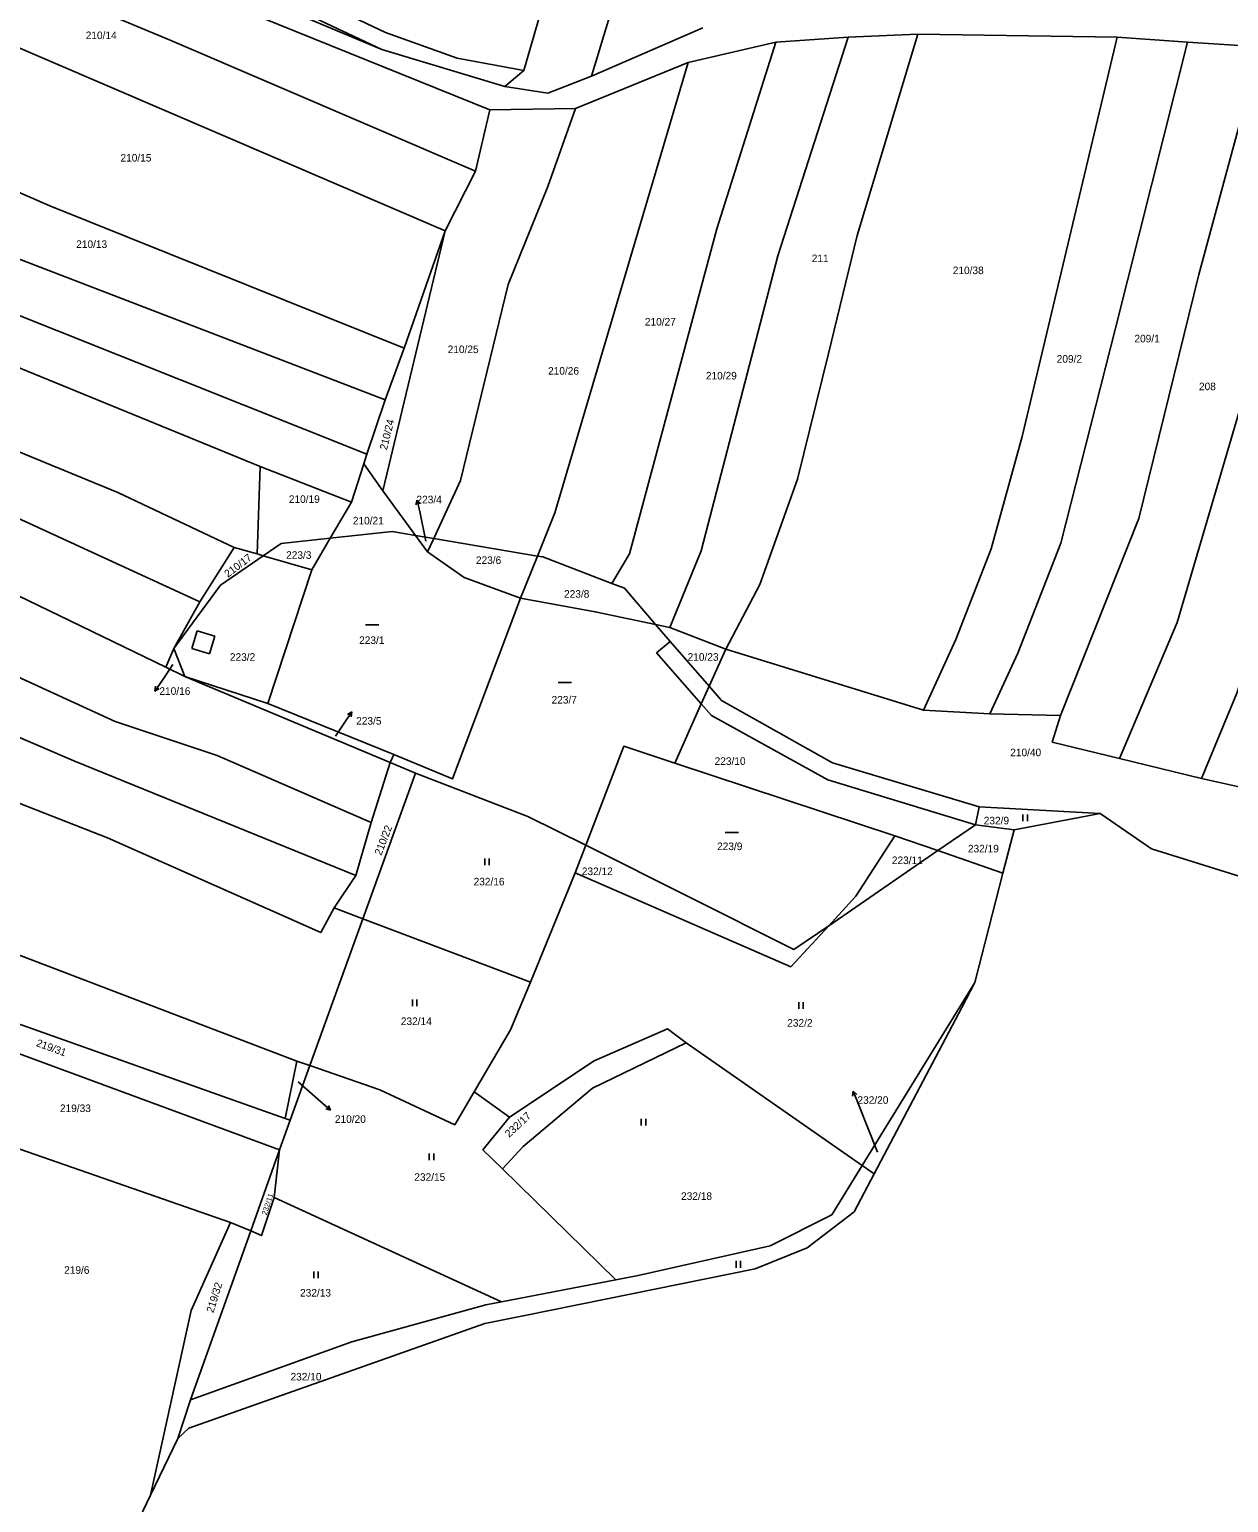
# Model space of a CAD drawing. Extents: x -746176 to -739709, y -1128407 to -1124482.
# Drawn here: x -742743.6 to -742474.2, y -1128024.5 to -1127693.8 of the extents above; entities that cross this region are included whole.
import ezdxf

# ---------------------------------------------------------------- set-up
doc = ezdxf.new("R2010")
doc.units = 0
for name, color, linetype in [('Vrstva 33', 7, 'Continuous'), ('Vrstva 42', 7, 'Continuous'), ('Vrstva 43', 7, 'Continuous'), ('Vrstva 44', 7, 'Continuous'), ('Vrstva 47', 7, 'Continuous')]:
    doc.layers.add(name, color=color, linetype=linetype)

msp = doc.modelspace()

# ---------------------------------------------------------------- linework, layer by layer
at = {"layer": 'Vrstva 33'}
for p, q in [((-742632.48, -1127703.04), (-742626.86, -1127683.46)), ((-742617.34, -1127704.25), (-742592.33, -1127693.42)), ((-742575.9, -1127696.61), (-742595.59, -1127701.21)), ((-742559.67, -1127695.56), (-742575.9, -1127696.61)), ((-742559.67, -1127695.56), (-742544.01, -1127694.88)), ((-742499.23, -1127695.56), (-742544.01, -1127694.88)), ((-742483.38, -1127696.63), (-742499.23, -1127695.56)), ((-742467.04, -1127697.67), (-742483.38, -1127696.63)), ((-742636.82, -1127706.57), (-742664.42, -1127698.33)), ((-742632.48, -1127703.04), (-742636.82, -1127706.57)), ((-742595.59, -1127701.21), (-742620.93, -1127711.51)), ((-742643.36, -1127725.63), (-742640.13, -1127711.82)), ((-742620.93, -1127711.51), (-742640.13, -1127711.82)), ((-742650.2, -1127739.03), (-742643.36, -1127725.63)), ((-742663.65, -1127776.96), (-742792.35, -1127727.57)), ((-742664.19, -1127797.36), (-742650.2, -1127739.03)), ((-742659.43, -1127765.34), (-742650.2, -1127739.03)), ((-742663.65, -1127776.96), (-742659.43, -1127765.34)), ((-742667.79, -1127789.16), (-742663.65, -1127776.96)), ((-742668.48, -1127791.31), (-742667.79, -1127789.16)), ((-742692.45, -1127811.55), (-742691.75, -1127791.9)), ((-742691.75, -1127791.9), (-742671.24, -1127799.9)), ((-742671.24, -1127799.9), (-742668.48, -1127791.31)), ((-742664.19, -1127797.36), (-742668.48, -1127791.31)), ((-742656.82, -1127807.4), (-742664.19, -1127797.36)), ((-742675.99, -1127807.99), (-742671.24, -1127799.9)), ((-742675.99, -1127807.99), (-742680.15, -1127815.09)), ((-742656.82, -1127807.4), (-742652.76, -1127808.09)), ((-742654.13, -1127811.06), (-742656.82, -1127807.4)), ((-742654.13, -1127811.06), (-742652.76, -1127808.09)), ((-742652.76, -1127808.09), (-742629.43, -1127812.04)), ((-742705.33, -1127822.31), (-742697.57, -1127810.08)), ((-742697.57, -1127810.08), (-742692.45, -1127811.55)), ((-742691.07, -1127811.95), (-742692.45, -1127811.55)), ((-742680.15, -1127815.09), (-742691.07, -1127811.95)), ((-742633.23, -1127821.48), (-742629.43, -1127812.04)), ((-742680.15, -1127815.09), (-742690.04, -1127845.16)), ((-742711.14, -1127832.79), (-742705.33, -1127822.31)), ((-742599.71, -1127828.08), (-742602.93, -1127827.4)), ((-742587.17, -1127832.97), (-742599.71, -1127828.08)), ((-742712.92, -1127837.01), (-742711.14, -1127832.79)), ((-742708.67, -1127839.06), (-742711.14, -1127832.79)), ((-742590.87, -1127841.26), (-742587.17, -1127832.97)), ((-742587.17, -1127832.97), (-742542.71, -1127846.65)), ((-742708.67, -1127839.06), (-742712.92, -1127837.01)), ((-742662.54, -1127858.41), (-742708.67, -1127839.06)), ((-742708.67, -1127839.06), (-742690.04, -1127845.16)), ((-742690.04, -1127845.16), (-742661.69, -1127856.62)), ((-742542.71, -1127846.65), (-742527.8, -1127847.44)), ((-742527.8, -1127847.44), (-742511.96, -1127847.84)), ((-742666.84, -1127871.89), (-742662.54, -1127858.41)), ((-742662.54, -1127858.41), (-742661.69, -1127856.62)), ((-742656.86, -1127860.79), (-742662.54, -1127858.41)), ((-742549.19, -1127874.82), (-742598.57, -1127858.52)), ((-742498.72, -1127857.52), (-742480.24, -1127862.01)), ((-742668.67, -1127893.45), (-742656.86, -1127860.79)), ((-742480.24, -1127862.01), (-742451.26, -1127868.39)), ((-742531.05, -1127872.36), (-742530.23, -1127868.37)), ((-742530.23, -1127868.37), (-742503.01, -1127869.85)), ((-742670.28, -1127883.77), (-742666.84, -1127871.89)), ((-742539.51, -1127878.17), (-742531.05, -1127872.36)), ((-742522.38, -1127873.53), (-742531.05, -1127872.36)), ((-742503.01, -1127869.85), (-742522.38, -1127873.53)), ((-742491.5, -1127877.75), (-742503.01, -1127869.85)), ((-742549.19, -1127874.82), (-742539.51, -1127878.17)), ((-742522.38, -1127873.53), (-742524.88, -1127883.24)), ((-742618.61, -1127876.98), (-742620.99, -1127883.17)), ((-742539.51, -1127878.17), (-742564.03, -1127895.02)), ((-742524.88, -1127883.24), (-742539.51, -1127878.17)), ((-742426.38, -1127898.15), (-742491.5, -1127877.75)), ((-742675.1, -1127891.02), (-742670.28, -1127883.77)), ((-742620.99, -1127883.17), (-742630.99, -1127907.7)), ((-742524.88, -1127883.24), (-742531.2, -1127907.76)), ((-742668.67, -1127893.45), (-742675.1, -1127891.02)), ((-742680.6, -1127926.45), (-742668.67, -1127893.45)), ((-742630.99, -1127907.7), (-742668.67, -1127893.45)), ((-742802.25, -1127897.14), (-742686.17, -1127938.31)), ((-742795.76, -1127905.39), (-742687.4, -1127945.34)), ((-742556.49, -1127948.86), (-742531.2, -1127907.76)), ((-742531.2, -1127907.76), (-742534.15, -1127913.36)), ((-742534.15, -1127913.36), (-742553.06, -1127949.33)), ((-742596.01, -1127921.34), (-742556.49, -1127948.86)), ((-742686.17, -1127938.31), (-742683.5, -1127925.44)), ((-742685.04, -1127938.71), (-742680.6, -1127926.45)), ((-742683.5, -1127925.44), (-742680.6, -1127926.45)), ((-742698.39, -1127961.68), (-742775.86, -1127934.72)), ((-742643.67, -1127932.31), (-742635.75, -1127937.99)), ((-742686.17, -1127938.31), (-742685.04, -1127938.71)), ((-742687.4, -1127945.34), (-742685.04, -1127938.71)), ((-742693.88, -1127963.5), (-742687.4, -1127945.34)), ((-742688.57, -1127956.03), (-742687.4, -1127945.34)), ((-742611.87, -1127974.55), (-742637.32, -1127949.65)), ((-742553.8, -1127950.73), (-742556.49, -1127948.86)), ((-742553.06, -1127949.33), (-742553.8, -1127950.73)), ((-742637.54, -1127979.49), (-742688.57, -1127956.03)), ((-742693.88, -1127963.5), (-742698.39, -1127961.68)), ((-742707.43, -1128001.51), (-742693.88, -1127963.5)), ((-742611.87, -1127974.55), (-742637.54, -1127979.49)), ((-742580.51, -1127972.05), (-742608.61, -1127977.73)), ((-742641.25, -1127984.32), (-742707.81, -1128007.87)), ((-742707.43, -1128001.51), (-742710.24, -1128010.19)), ((-742707.81, -1128007.87), (-742710.24, -1128010.19)), ((-742710.24, -1128010.19), (-742716.39, -1128022.92)), ((-742716.39, -1128022.92), (-742728.18, -1128047.33))]:
    msp.add_line(p, q, dxfattribs=at)
for points in [[(-742617.34, -1127704.25), (-742592.59, -1127622.78), (-742562.59, -1127531.26), (-742547.11, -1127485.27), (-742537.81, -1127453.81)], [(-742849.54, -1127613.47), (-742848.76, -1127613.6), (-742786.4, -1127635.17), (-742756.11, -1127640.29), (-742704.21, -1127675.14), (-742663.56, -1127694.46), (-742647.49, -1127700.26), (-742632.48, -1127703.04)], [(-742664.42, -1127698.33), (-742705.7, -1127678.8), (-742757.77, -1127644.27), (-742759.53, -1127644.48)], [(-742763.36, -1127654.17), (-742748.4, -1127660.64), (-742692.32, -1127686.56), (-742664.42, -1127698.33)], [(-742640.13, -1127711.82), (-742707.48, -1127684.6), (-742751.48, -1127663.32), (-742764.73, -1127657.63)], [(-742643.36, -1127725.63), (-742711.98, -1127696.17), (-742770.35, -1127671.87)], [(-742775.45, -1127684.77), (-742763.82, -1127690.28), (-742650.2, -1127739.03)], [(-742612.72, -1127818.18), (-742608.79, -1127811.54), (-742589.16, -1127738.55), (-742575.9, -1127696.61)], [(-742599.71, -1127828.08), (-742592.67, -1127810.85), (-742575.45, -1127744.63), (-742559.67, -1127695.56)], [(-742544.01, -1127694.88), (-742557.6, -1127740.07), (-742564.08, -1127766.54), (-742571.03, -1127794.76), (-742579.48, -1127818.4), (-742587.17, -1127832.97)], [(-742499.23, -1127695.56), (-742520.53, -1127785.2), (-742527.52, -1127810.4), (-742535.44, -1127830.74), (-742542.71, -1127846.65)], [(-742483.38, -1127696.63), (-742499.62, -1127760.84), (-742511.87, -1127809.1), (-742521.5, -1127833.81), (-742527.8, -1127847.44)], [(-742467.04, -1127697.67), (-742480.9, -1127748.82), (-742494.32, -1127803.6), (-742511.96, -1127847.84)], [(-742449.94, -1127699.44), (-742466.13, -1127760.26), (-742485.77, -1127826.93), (-742498.72, -1127857.52)], [(-742629.43, -1127812.04), (-742625.54, -1127802.36), (-742595.59, -1127701.21)], [(-742432.12, -1127702.08), (-742464.27, -1127819.17), (-742472.32, -1127842.8), (-742480.24, -1127862.01)], [(-742878.82, -1127704.23), (-742859.56, -1127712.24), (-742858.85, -1127709.24), (-742793.05, -1127739.22), (-742667.79, -1127789.16)], [(-742636.82, -1127706.57), (-742627.13, -1127708.08), (-742617.34, -1127704.25)], [(-742691.75, -1127791.9), (-742786.9, -1127753.03), (-742859.54, -1127721.45), (-742886.72, -1127710.02)], [(-742659.43, -1127765.34), (-742739.02, -1127733.43), (-742786.49, -1127712.73)], [(-742652.76, -1127808.09), (-742646.74, -1127795.08), (-742636.01, -1127751.08), (-742627.15, -1127729.06), (-742620.93, -1127711.51)], [(-742697.57, -1127810.08), (-742723.74, -1127797.75), (-742779.52, -1127774.85), (-742849.36, -1127744.61), (-742849.6, -1127747), (-742896.29, -1127726.42), (-742905.07, -1127723.45)], [(-742705.33, -1127822.31), (-742752.11, -1127800.85), (-742855.88, -1127756.96), (-742856.57, -1127758.28), (-742916.95, -1127732.14)], [(-742929.76, -1127741.52), (-742892.25, -1127757.26), (-742839.56, -1127779.37), (-742839.56, -1127777.92), (-742777.16, -1127805.95), (-742712.92, -1127837.01)], [(-742942.9, -1127751.14), (-742921.78, -1127760.46), (-742847.12, -1127793.15), (-742812.02, -1127809), (-742724.3, -1127849.19), (-742701.43, -1127856.81), (-742666.84, -1127871.89)], [(-742670.28, -1127883.77), (-742733.59, -1127858.01), (-742796.71, -1127830.89), (-742912.22, -1127779.41), (-742955.04, -1127760.03)], [(-742691.07, -1127811.95), (-742687.04, -1127809.18), (-742675.99, -1127807.99)], [(-742656.82, -1127807.4), (-742662.11, -1127806.5), (-742675.99, -1127807.99)], [(-742711.14, -1127832.79), (-742700.65, -1127818.54), (-742691.07, -1127811.95)], [(-742633.23, -1127821.48), (-742645.94, -1127816.84), (-742654.13, -1127811.06)], [(-742629.43, -1127812.04), (-742628.23, -1127812.24), (-742612.72, -1127818.18)], [(-742612.72, -1127818.18), (-742609.89, -1127819.27), (-742602.93, -1127827.4)], [(-742661.69, -1127856.62), (-742648.57, -1127862.05), (-742633.23, -1127821.48)], [(-742602.93, -1127827.4), (-742616.47, -1127824.52), (-742633.23, -1127821.48)], [(-742602.93, -1127827.4), (-742599.66, -1127831.22), (-742590.87, -1127841.26)], [(-742833.19, -1127833.4), (-742726.08, -1127875.32), (-742678.13, -1127896.57), (-742675.1, -1127891.02)], [(-742598.57, -1127858.52), (-742592.64, -1127845.23), (-742590.87, -1127841.26)], [(-742590.87, -1127841.26), (-742588.09, -1127844.43), (-742563.17, -1127858.44), (-742530.23, -1127868.37)], [(-742511.96, -1127847.84), (-742513.81, -1127853.78), (-742498.72, -1127857.52)], [(-742618.61, -1127876.98), (-742610.06, -1127854.73), (-742598.57, -1127858.52)], [(-742656.86, -1127860.79), (-742631.6, -1127870.48), (-742618.61, -1127876.98)], [(-742683.5, -1127925.44), (-742813.75, -1127875.71), (-742817.94, -1127875.01)], [(-742564.03, -1127895.02), (-742557.92, -1127888.41), (-742549.19, -1127874.82)], [(-742618.61, -1127876.98), (-742571.86, -1127900.4), (-742564.03, -1127895.02)], [(-742564.03, -1127895.02), (-742572.56, -1127904.25), (-742620.99, -1127883.17)], [(-742630.99, -1127907.7), (-742635.51, -1127918.42), (-742643.67, -1127932.31)], [(-742635.75, -1127937.99), (-742616.69, -1127925.34), (-742600.23, -1127918.18), (-742596.01, -1127921.34)], [(-742637.32, -1127949.65), (-742632.63, -1127944.62), (-742617.12, -1127931.51), (-742596.01, -1127921.34)], [(-742680.6, -1127926.45), (-742664.9, -1127931.91), (-742648.02, -1127939.7), (-742643.67, -1127932.31)], [(-742637.32, -1127949.65), (-742641.69, -1127945.38), (-742635.75, -1127937.99)], [(-742556.49, -1127948.86), (-742563.33, -1127959.98), (-742577.15, -1127966.9), (-742606.85, -1127973.58), (-742611.87, -1127974.55)], [(-742553.8, -1127950.73), (-742558.28, -1127959.25), (-742568.84, -1127967.38), (-742580.51, -1127972.05)], [(-742693.88, -1127963.5), (-742691.48, -1127964.62), (-742688.57, -1127956.03)], [(-742716.39, -1128022.92), (-742707.26, -1127981.44), (-742698.39, -1127961.68)], [(-742608.61, -1127977.73), (-742632.32, -1127982.52), (-742641.25, -1127984.32)], [(-742637.54, -1127979.49), (-742641.03, -1127980.16), (-742671.12, -1127988.44), (-742707.43, -1128001.51)]]:
    msp.add_lwpolyline(points, dxfattribs=at)
at = {"layer": 'Vrstva 43'}
for p, q in [((-742656.46, -1127799.46), (-742656.75, -1127800.54)), ((-742655.84, -1127802.39), (-742656.46, -1127799.46)), ((-742656.46, -1127799.46), (-742655.77, -1127800.33)), ((-742654.53, -1127808.7), (-742655.84, -1127802.39)), ((-742711.38, -1127836.41), (-742713.71, -1127839.86)), ((-742713.71, -1127839.86), (-742715.39, -1127842.35)), ((-742715.39, -1127842.35), (-742715.24, -1127841.24)), ((-742715.39, -1127842.35), (-742714.41, -1127841.8)), ((-742672.86, -1127849.53), (-742671.18, -1127847.04)), ((-742671.18, -1127847.04), (-742672.16, -1127847.59)), ((-742671.18, -1127847.04), (-742671.33, -1127848.15)), ((-742674.85, -1127852.46), (-742672.86, -1127849.53)), ((-742683.2, -1127930.09), (-742678.21, -1127934.48)), ((-742678.21, -1127934.48), (-742675.95, -1127936.45)), ((-742558.56, -1127932.2), (-742558.65, -1127933.31)), ((-742557.44, -1127934.98), (-742558.56, -1127932.2)), ((-742558.56, -1127932.2), (-742557.72, -1127932.94)), ((-742553.07, -1127945.89), (-742557.44, -1127934.98)), ((-742675.95, -1127936.45), (-742677.03, -1127936.17)), ((-742675.95, -1127936.45), (-742676.37, -1127935.41))]:
    msp.add_line(p, q, dxfattribs=at)
at = {"layer": 'Vrstva 44'}
for p, q in [((-742668.11, -1127827.45), (-742665.11, -1127827.45)), ((-742624.81, -1127840.39), (-742621.81, -1127840.39)), ((-742520.38, -1127871.59), (-742520.38, -1127870.09)), ((-742519.38, -1127871.59), (-742519.38, -1127870.09)), ((-742587.26, -1127874.09), (-742584.26, -1127874.09)), ((-742641.3, -1127881.42), (-742641.3, -1127879.92)), ((-742640.3, -1127881.42), (-742640.3, -1127879.92)), ((-742657.55, -1127913.08), (-742657.55, -1127911.58)), ((-742656.55, -1127913.08), (-742656.55, -1127911.58)), ((-742570.77, -1127913.71), (-742570.77, -1127912.21)), ((-742569.77, -1127913.71), (-742569.77, -1127912.21)), ((-742606.13, -1127939.86), (-742606.13, -1127938.36)), ((-742605.13, -1127939.86), (-742605.13, -1127938.36)), ((-742653.75, -1127947.69), (-742653.75, -1127946.19)), ((-742652.75, -1127947.69), (-742652.75, -1127946.19)), ((-742584.82, -1127971.81), (-742584.82, -1127970.31)), ((-742583.82, -1127971.81), (-742583.82, -1127970.31)), ((-742679.69, -1127974.16), (-742679.69, -1127972.66)), ((-742678.69, -1127974.16), (-742678.69, -1127972.66))]:
    msp.add_line(p, q, dxfattribs=at)
at = {"layer": 'Vrstva 47'}
for p, q in [((-742707.09, -1127832.82), (-742705.88, -1127828.82)), ((-742705.88, -1127828.82), (-742701.93, -1127830.01)), ((-742703.14, -1127834.01), (-742701.93, -1127830.01)), ((-742602.7, -1127833.78), (-742599.66, -1127831.22)), ((-742707.09, -1127832.82), (-742703.14, -1127834.01)), ((-742602.7, -1127833.78), (-742592.64, -1127845.23)), ((-742592.64, -1127845.23), (-742590.38, -1127847.8)), ((-742590.38, -1127847.8), (-742564.19, -1127862.31)), ((-742564.19, -1127862.31), (-742531.05, -1127872.36))]:
    msp.add_line(p, q, dxfattribs=at)

# ---------------------------------------------------------------- texts
at = {"layer": 'Vrstva 42'}
for s, p in [('210/14', (-742730.94, -1127695.96)), ('210/15', (-742723.13, -1127723.46)), ('210/13', (-742733.08, -1127742.86)), ('211', (-742567.83, -1127746.04)), ('210/38', (-742536.15, -1127748.73)), ('210/27', (-742605.32, -1127760.28)), ('209/1', (-742495.34, -1127764.05)), ('210/25', (-742649.62, -1127766.46)), ('210/26', (-742627.07, -1127771.3)), ('209/2', (-742512.79, -1127768.61)), ('210/29', (-742591.62, -1127772.38)), ('208', (-742480.84, -1127774.79)), ('210/19', (-742685.31, -1127800.1)), ('223/4', (-742656.63, -1127800.19)), ('210/21', (-742670.93, -1127804.93)), ('223/3', (-742685.92, -1127812.65)), ('223/6', (-742643.28, -1127813.81)), ('223/8', (-742623.48, -1127821.38)), ('223/1', (-742669.52, -1127831.77)), ('223/2', (-742698.55, -1127835.55)), ('210/23', (-742595.72, -1127835.54)), ('210/16', (-742714.39, -1127843.19)), ('223/7', (-742626.28, -1127845.15)), ('223/5', (-742670.18, -1127849.88)), ('210/40', (-742523.24, -1127856.97)), ('223/10', (-742589.65, -1127858.92)), ('232/9', (-742529.19, -1127872.27)), ('223/9', (-742589.1, -1127878.05)), ('232/19', (-742532.75, -1127878.57)), ('232/12', (-742619.49, -1127883.66)), ('223/11', (-742549.84, -1127881.19)), ('232/16', (-742643.8, -1127885.98)), ('232/14', (-742660.14, -1127917.33)), ('232/2', (-742573.34, -1127917.7)), ('219/33', (-742736.74, -1127936.87)), ('232/20', (-742557.56, -1127935.02)), ('210/20', (-742674.96, -1127939.29)), ('232/15', (-742657.12, -1127952.31)), ('232/18', (-742597.19, -1127956.59)), ('219/6', (-742735.79, -1127973.19)), ('232/13', (-742682.79, -1127978.29)), ('232/10', (-742684.93, -1127997.14))]:
    msp.add_text(s, height=1.7, dxfattribs=at).set_placement(p)
for s, height, rotation, p in [('210/24', 1.7, 76, (-742663.28, -1127788.34)), ('210/17', 1.7, 37, (-742699, -1127816.93)), ('210/22', 1.7, 69, (-742664.54, -1127879.36)), ('219/31', 1.7, 340, (-742742.21, -1127922.02)), ('232/17', 1.7, 43, (-742635.81, -1127942.69)), ('232/11', 1.19, 72, (-742690.31, -1127960.13)), ('219/32', 1.7, 73, (-742702.26, -1127982.07))]:
    msp.add_text(s, height=height, rotation=rotation, dxfattribs=at).set_placement(p)

doc.saveas('drawing.dxf')
